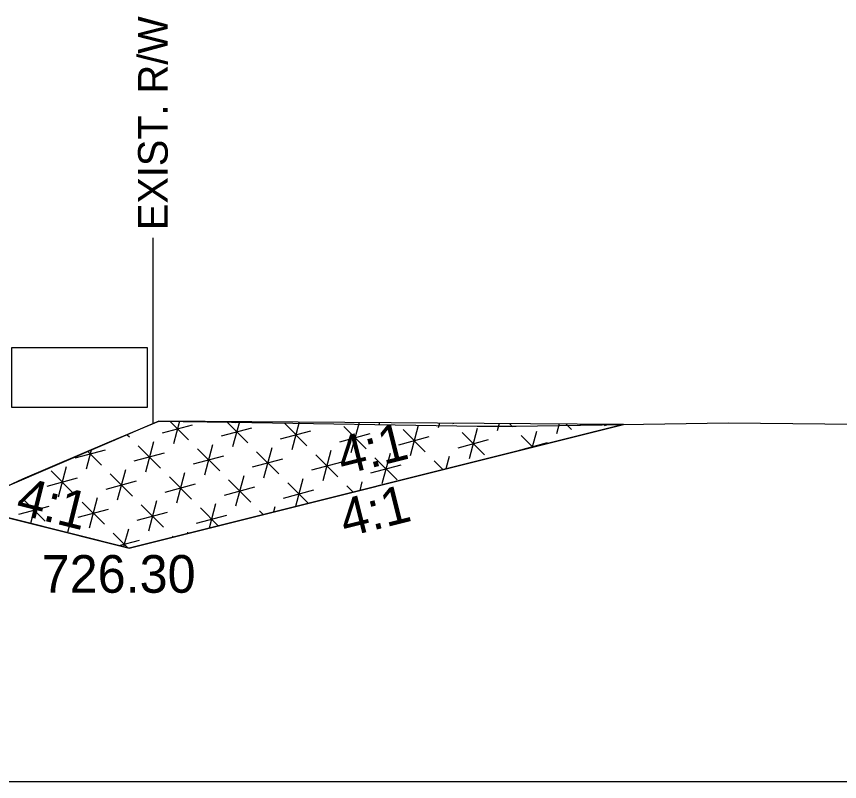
# Model space of a CAD drawing. Extents: x -26 to 4303, y -10 to 9577.
# Drawn here: x 4174.51 to 4207.3, y 3000 to 3030.46 of the extents above; entities that cross this region are included whole.
import ezdxf

# ---------------------------------------------------------------- set-up
doc = ezdxf.new("R2010")
doc.units = 0
for name, color, linetype in [('Old_Level_2', 7, 'Continuous'), ('Pattern 3', 7, 'Continuous'), ('Prop CMT Pvmt Course 2 Wedge', 7, 'Continuous'), ('Prop CMT Slope Grass', 7, 'Continuous'), ('Prop XS DDE Elevations', 7, 'Continuous'), ('Prop XS Ditch Standard Text', 7, 'Continuous'), ('Prop XS Hydro Elevations', 7, 'Continuous'), ('Prop XS Side Slope Text', 7, 'Continuous')]:
    doc.layers.add(name, color=color, linetype=linetype)

msp = doc.modelspace()

# ---------------------------------------------------------------- linework, layer by layer
at = {"layer": 'Old_Level_2'}
msp.add_line((4150, 3000), (4300, 3000), dxfattribs=at)
msp.add_line((4150, 3000), (4300, 3000), dxfattribs=at)
at = {"layer": 'Pattern 3'}
for p, q in [((4180.324, 3013.883), (4181.531, 3014.206)), ((4180.324, 3013.883), (4181.531, 3014.206)), ((4180.624, 3014.348), (4181.369, 3013.602)), ((4180.624, 3014.348), (4181.369, 3013.602)), ((4181.008, 3014.345), (4180.766, 3013.441)), ((4181.008, 3014.345), (4180.766, 3013.441)), ((4182.878, 3014.332), (4183.726, 3013.484)), ((4182.878, 3014.332), (4183.726, 3013.484)), ((4183.392, 3014.328), (4183.122, 3013.322)), ((4183.392, 3014.328), (4183.122, 3013.322)), ((4183.199, 3014.33), (4183.245, 3014.284)), ((4185.198, 3014.25), (4186.082, 3013.366)), ((4185.198, 3014.25), (4186.082, 3013.366)), ((4185.775, 3014.311), (4185.479, 3013.204)), ((4185.775, 3014.311), (4185.479, 3013.204)), ((4188.158, 3014.293), (4187.835, 3013.085)), ((4188.977, 3014.289), (4188.954, 3014.204)), ((4191.36, 3014.272), (4191.31, 3014.086)), ((4191.894, 3014.268), (4191.914, 3014.248)), ((4193.744, 3014.255), (4193.667, 3013.968)), ((4194.148, 3014.252), (4194.271, 3014.129)), ((4196.128, 3014.238), (4196.023, 3013.849)), ((4196.402, 3014.236), (4196.627, 3014.011)), ((4197.938, 3014.173), (4198.128, 3014.224)), ((4198.511, 3014.221), (4198.498, 3014.172)), ((4198.656, 3014.22), (4198.663, 3014.213)), ((4198.679, 3014.22), (4198.681, 3014.218)), ((4182.68, 3013.764), (4183.888, 3014.088)), ((4182.68, 3013.764), (4183.888, 3014.088)), ((4185.037, 3013.646), (4186.244, 3013.969)), ((4185.037, 3013.646), (4186.244, 3013.969)), ((4187.555, 3014.131), (4188.439, 3013.247)), ((4189.911, 3014.013), (4190.795, 3013.129)), ((4190.515, 3014.174), (4190.191, 3012.967)), ((4192.268, 3013.894), (4193.152, 3013.01)), ((4192.871, 3014.056), (4192.548, 3012.849)), ((4195.228, 3013.938), (4195.06, 3013.312)), ((4197.495, 3013.931), (4197.492, 3013.92)), ((4178.418, 3013.592), (4178.409, 3013.559)), ((4178.418, 3013.592), (4178.409, 3013.559)), ((4178.924, 3013.81), (4179.013, 3013.721)), ((4178.924, 3013.81), (4179.013, 3013.721)), ((4187.393, 3013.527), (4188.6, 3013.851)), ((4189.749, 3013.409), (4190.957, 3013.732)), ((4192.106, 3013.291), (4193.313, 3013.614)), ((4194.624, 3013.776), (4195.082, 3013.318)), ((4179.366, 3013.367), (4180.25, 3012.483)), ((4179.366, 3013.367), (4180.25, 3012.483)), ((4179.97, 3013.529), (4179.647, 3012.322)), ((4179.97, 3013.529), (4179.647, 3012.322)), ((4181.723, 3013.249), (4182.607, 3012.365)), ((4181.723, 3013.249), (4182.607, 3012.365)), ((4182.327, 3013.411), (4182.003, 3012.203)), ((4182.327, 3013.411), (4182.003, 3012.203)), ((4184.683, 3013.292), (4184.359, 3012.085)), ((4184.683, 3013.292), (4184.359, 3012.085)), ((4194.462, 3013.172), (4195.67, 3013.496)), ((4176.848, 3012.882), (4178.056, 3013.206)), ((4176.848, 3012.882), (4178.056, 3013.206)), ((4177.492, 3013.194), (4177.29, 3012.44)), ((4177.492, 3013.194), (4177.29, 3012.44)), ((4177.359, 3013.137), (4177.894, 3012.602)), ((4177.359, 3013.137), (4177.894, 3012.602)), ((4179.205, 3012.764), (4180.412, 3013.087)), ((4179.205, 3012.764), (4180.412, 3013.087)), ((4181.561, 3012.645), (4182.769, 3012.969)), ((4181.561, 3012.645), (4182.769, 3012.969)), ((4184.079, 3013.13), (4184.963, 3012.247)), ((4184.079, 3013.13), (4184.963, 3012.247)), ((4186.436, 3013.012), (4187.32, 3012.128)), ((4186.436, 3013.012), (4187.32, 3012.128)), ((4187.039, 3013.174), (4186.716, 3011.966)), ((4187.039, 3013.174), (4186.716, 3011.966)), ((4188.792, 3012.894), (4189.676, 3012.01)), ((4188.792, 3012.894), (4189.676, 3012.01)), ((4189.396, 3013.055), (4189.072, 3011.848)), ((4189.396, 3013.055), (4189.072, 3011.848)), ((4191.752, 3012.937), (4191.623, 3012.453)), ((4183.918, 3012.527), (4185.125, 3012.85)), ((4183.918, 3012.527), (4185.125, 3012.85)), ((4186.274, 3012.408), (4187.481, 3012.732)), ((4186.274, 3012.408), (4187.481, 3012.732)), ((4188.63, 3012.29), (4189.838, 3012.613)), ((4188.63, 3012.29), (4189.838, 3012.613)), ((4191.149, 3012.775), (4191.501, 3012.423)), ((4175.891, 3012.367), (4176.775, 3011.483)), ((4175.891, 3012.367), (4176.775, 3011.483)), ((4176.495, 3012.528), (4176.171, 3011.321)), ((4176.495, 3012.528), (4176.171, 3011.321)), ((4178.247, 3012.248), (4179.131, 3011.364)), ((4178.247, 3012.248), (4179.131, 3011.364)), ((4178.851, 3012.41), (4178.528, 3011.203)), ((4178.851, 3012.41), (4178.528, 3011.203)), ((4181.208, 3012.292), (4180.884, 3011.084)), ((4181.208, 3012.292), (4180.884, 3011.084)), ((4175.729, 3011.763), (4176.937, 3012.087)), ((4175.729, 3011.763), (4176.937, 3012.087)), ((4178.086, 3011.645), (4179.293, 3011.968)), ((4178.086, 3011.645), (4179.293, 3011.968)), ((4180.604, 3012.13), (4181.488, 3011.246)), ((4180.604, 3012.13), (4181.488, 3011.246)), ((4182.96, 3012.011), (4183.844, 3011.128)), ((4182.96, 3012.011), (4183.844, 3011.128)), ((4183.564, 3012.173), (4183.24, 3010.966)), ((4183.564, 3012.173), (4183.24, 3010.966)), ((4185.92, 3012.055), (4185.625, 3010.954)), ((4185.92, 3012.055), (4185.625, 3010.954)), ((4188.277, 3011.936), (4188.185, 3011.594)), ((4188.277, 3011.936), (4188.185, 3011.594)), ((4180.442, 3011.526), (4181.649, 3011.85)), ((4180.442, 3011.526), (4181.649, 3011.85)), ((4182.799, 3011.408), (4184.006, 3011.731)), ((4182.799, 3011.408), (4184.006, 3011.731)), ((4185.155, 3011.289), (4186.362, 3011.613)), ((4185.155, 3011.289), (4186.362, 3011.613)), ((4185.317, 3011.893), (4186.13, 3011.08)), ((4185.317, 3011.893), (4186.13, 3011.08)), ((4187.673, 3011.775), (4187.92, 3011.527)), ((4187.673, 3011.775), (4187.92, 3011.527)), ((4174.772, 3011.248), (4175.656, 3010.364)), ((4174.772, 3011.248), (4175.656, 3010.364)), ((4175.376, 3011.409), (4175.073, 3010.279)), ((4175.376, 3011.409), (4175.073, 3010.279)), ((4177.732, 3011.291), (4177.409, 3010.084)), ((4177.732, 3011.291), (4177.409, 3010.084)), ((4174.61, 3010.644), (4175.818, 3010.968)), ((4174.61, 3010.644), (4175.818, 3010.968)), ((4177.128, 3011.129), (4178.012, 3010.245)), ((4177.128, 3011.129), (4178.012, 3010.245)), ((4179.485, 3011.011), (4180.369, 3010.127)), ((4179.485, 3011.011), (4180.369, 3010.127)), ((4180.089, 3011.173), (4179.765, 3009.965)), ((4180.089, 3011.173), (4179.765, 3009.965)), ((4182.445, 3011.054), (4182.188, 3010.094)), ((4182.445, 3011.054), (4182.188, 3010.094)), ((4184.801, 3010.936), (4184.747, 3010.734)), ((4184.801, 3010.936), (4184.747, 3010.734)), ((4176.967, 3010.526), (4178.174, 3010.849)), ((4176.967, 3010.526), (4178.174, 3010.849)), ((4179.323, 3010.407), (4180.53, 3010.731)), ((4179.323, 3010.407), (4180.53, 3010.731)), ((4181.68, 3010.289), (4182.887, 3010.612)), ((4181.68, 3010.289), (4182.887, 3010.612)), ((4181.841, 3010.892), (4182.549, 3010.185)), ((4181.841, 3010.892), (4182.549, 3010.185)), ((4184.198, 3010.774), (4184.34, 3010.632)), ((4184.198, 3010.774), (4184.34, 3010.632)), ((4176.613, 3010.172), (4176.543, 3009.912)), ((4176.613, 3010.172), (4176.543, 3009.912)), ((4178.97, 3010.054), (4178.782, 3009.352)), ((4178.97, 3010.054), (4178.782, 3009.352)), ((4181.326, 3009.935), (4181.31, 3009.875)), ((4178.366, 3009.892), (4178.947, 3009.311)), ((4178.366, 3009.892), (4178.947, 3009.311)), ((4178.606, 3009.396), (4179.411, 3009.612)), ((4178.606, 3009.396), (4179.411, 3009.612)), ((4180.722, 3009.773), (4180.759, 3009.737))]:
    msp.add_line(p, q, dxfattribs=at)
for points in [[(4174.325, 3017.288), (4179.718, 3017.288), (4179.718, 3014.887), (4174.325, 3014.887)], [(4161.951, 3011.111), (4161.952, 3010.723), (4171.307, 3010.536), (4171.314, 3011.219), (4179, 3009.297), (4198.689, 3014.22), (4180.18, 3014.351), (4173.965, 3011.675), (4170.309, 3011.12), (4168.855, 3010.89), (4167.944, 3010.745), (4165.196, 3010.9), (4163.168, 3011.029)]]:
    msp.add_lwpolyline(points, close=True, dxfattribs=at)
at = {"layer": 'Prop CMT Pvmt Course 2 Wedge'}
msp.add_lwpolyline([(4169, 3011.457), (4171, 3011.297), (4179, 3009.297), (4198.689, 3014.22)], dxfattribs=at)
at = {"layer": 'Prop CMT Slope Grass'}
msp.add_lwpolyline([(4173.965, 3011.675), (4174.763, 3012.057), (4178.222, 3013.521), (4180.18, 3014.351), (4183.081, 3014.305), (4192.872, 3014.152), (4194.423, 3014.15), (4202.877, 3014.288), (4211.825, 3014.193)], dxfattribs=at)
at = {"layer": 'Prop XS DDE Elevations'}
msp.add_lwpolyline([(4171.166, 3011.256), (4173.286, 3011.592), (4173.965, 3011.675), (4174.763, 3012.057), (4178.222, 3013.521), (4180.18, 3014.351), (4183.081, 3014.305), (4192.872, 3014.152), (4194.423, 3014.15), (4198.689, 3014.22), (4179, 3009.297), (4174.465, 3010.431)], close=True, dxfattribs=at)
at = {"layer": 'Prop XS Ditch Standard Text'}
msp.add_line((4179.946, 3021.653), (4179.946, 3014.252), dxfattribs=at)

# ---------------------------------------------------------------- texts
at = {"layer": 'Pattern 3'}
msp.add_text('4:1', height=1.5, rotation=14.0362, dxfattribs=at).set_placement((4187.509, 3012.198))
msp.add_text('4:1', height=1.5, rotation=14.0362, dxfattribs=at).set_placement((4187.509, 3012.198))
at = {"layer": 'Prop XS Ditch Standard Text'}
msp.add_text('EXIST. R/W', height=1.1811, rotation=90, dxfattribs=at).set_placement((4180.537, 3021.956))
at = {"layer": 'Prop XS Hydro Elevations'}
msp.add_text('726.30', height=1.5, dxfattribs=at).set_placement((4175.514, 3007.516))
at = {"layer": 'Prop XS Side Slope Text'}
for rotation, p in [(345.9638, (4174.43, 3010.677)), (14.0362, (4187.61, 3009.72))]:
    msp.add_text('4:1', height=1.5, rotation=rotation, dxfattribs=at).set_placement(p)

doc.saveas('drawing.dxf')
